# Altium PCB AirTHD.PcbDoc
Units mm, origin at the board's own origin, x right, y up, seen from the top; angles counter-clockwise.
Board outline 25.5 x 27.05 mm, 2 copper layers (Top Layer, Bottom Layer); 29 components, 49 nets, 170 pads, 71 vias.
Unrouted connection lines stored in the file: 1.
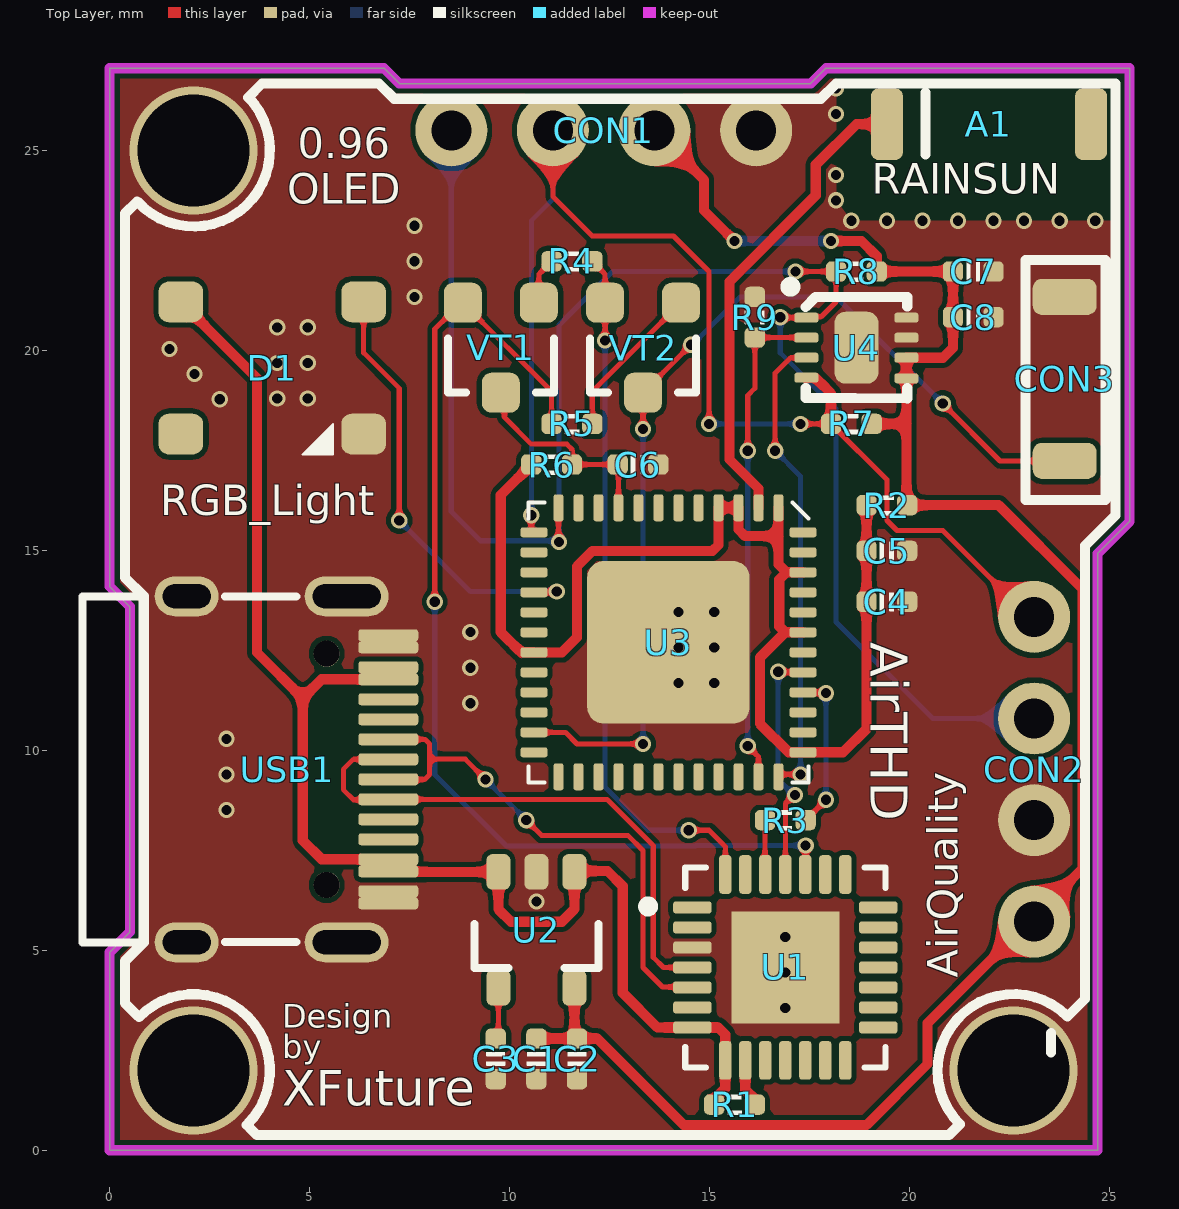
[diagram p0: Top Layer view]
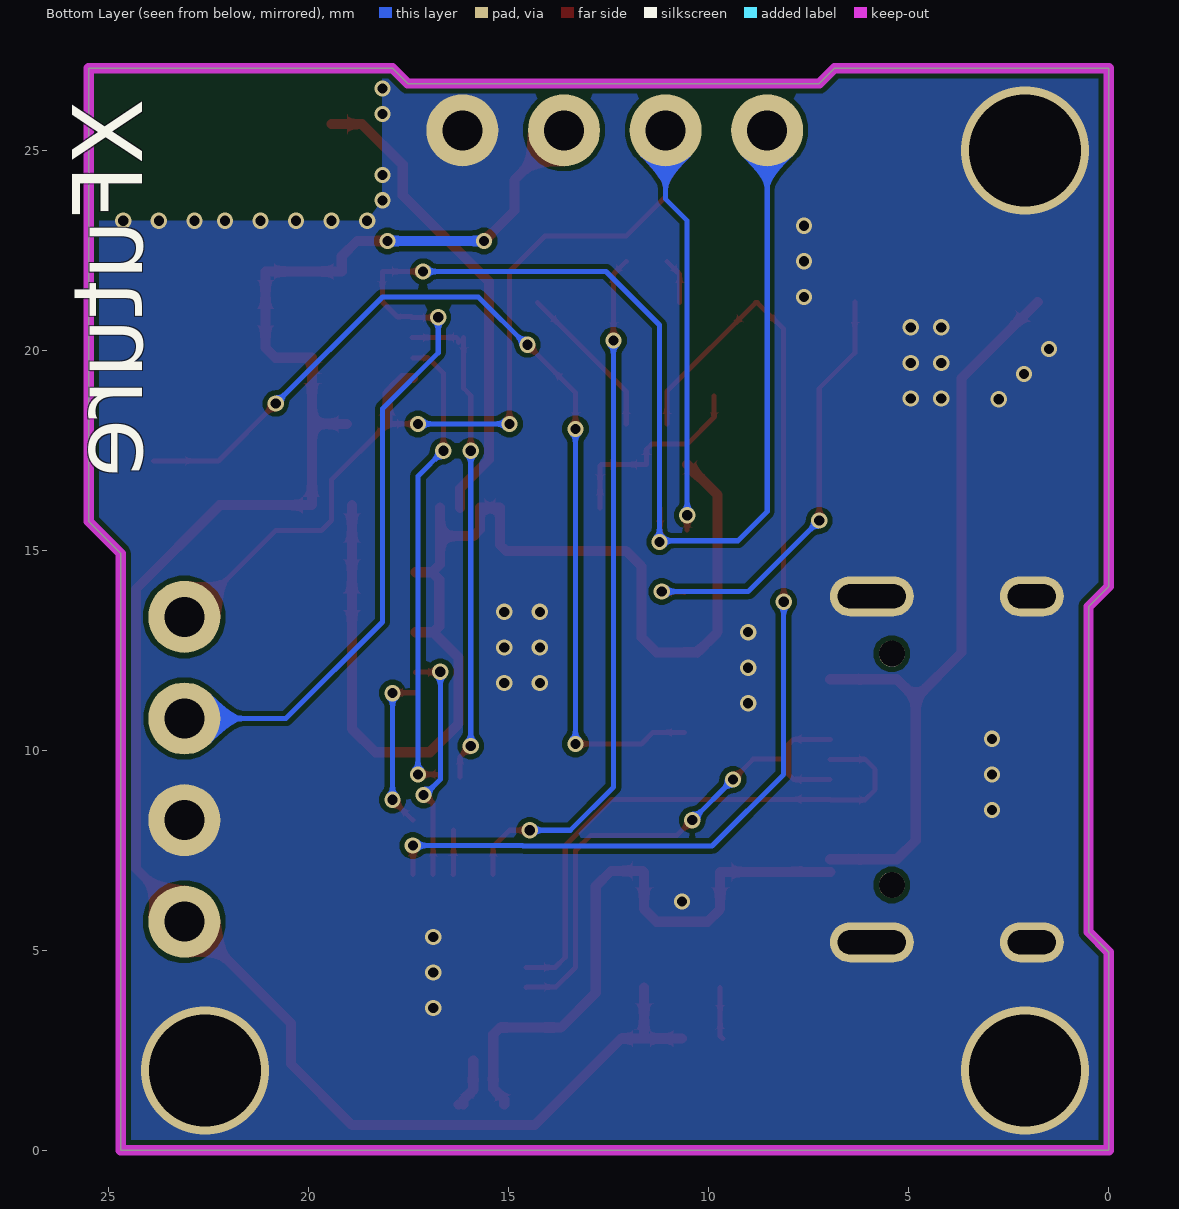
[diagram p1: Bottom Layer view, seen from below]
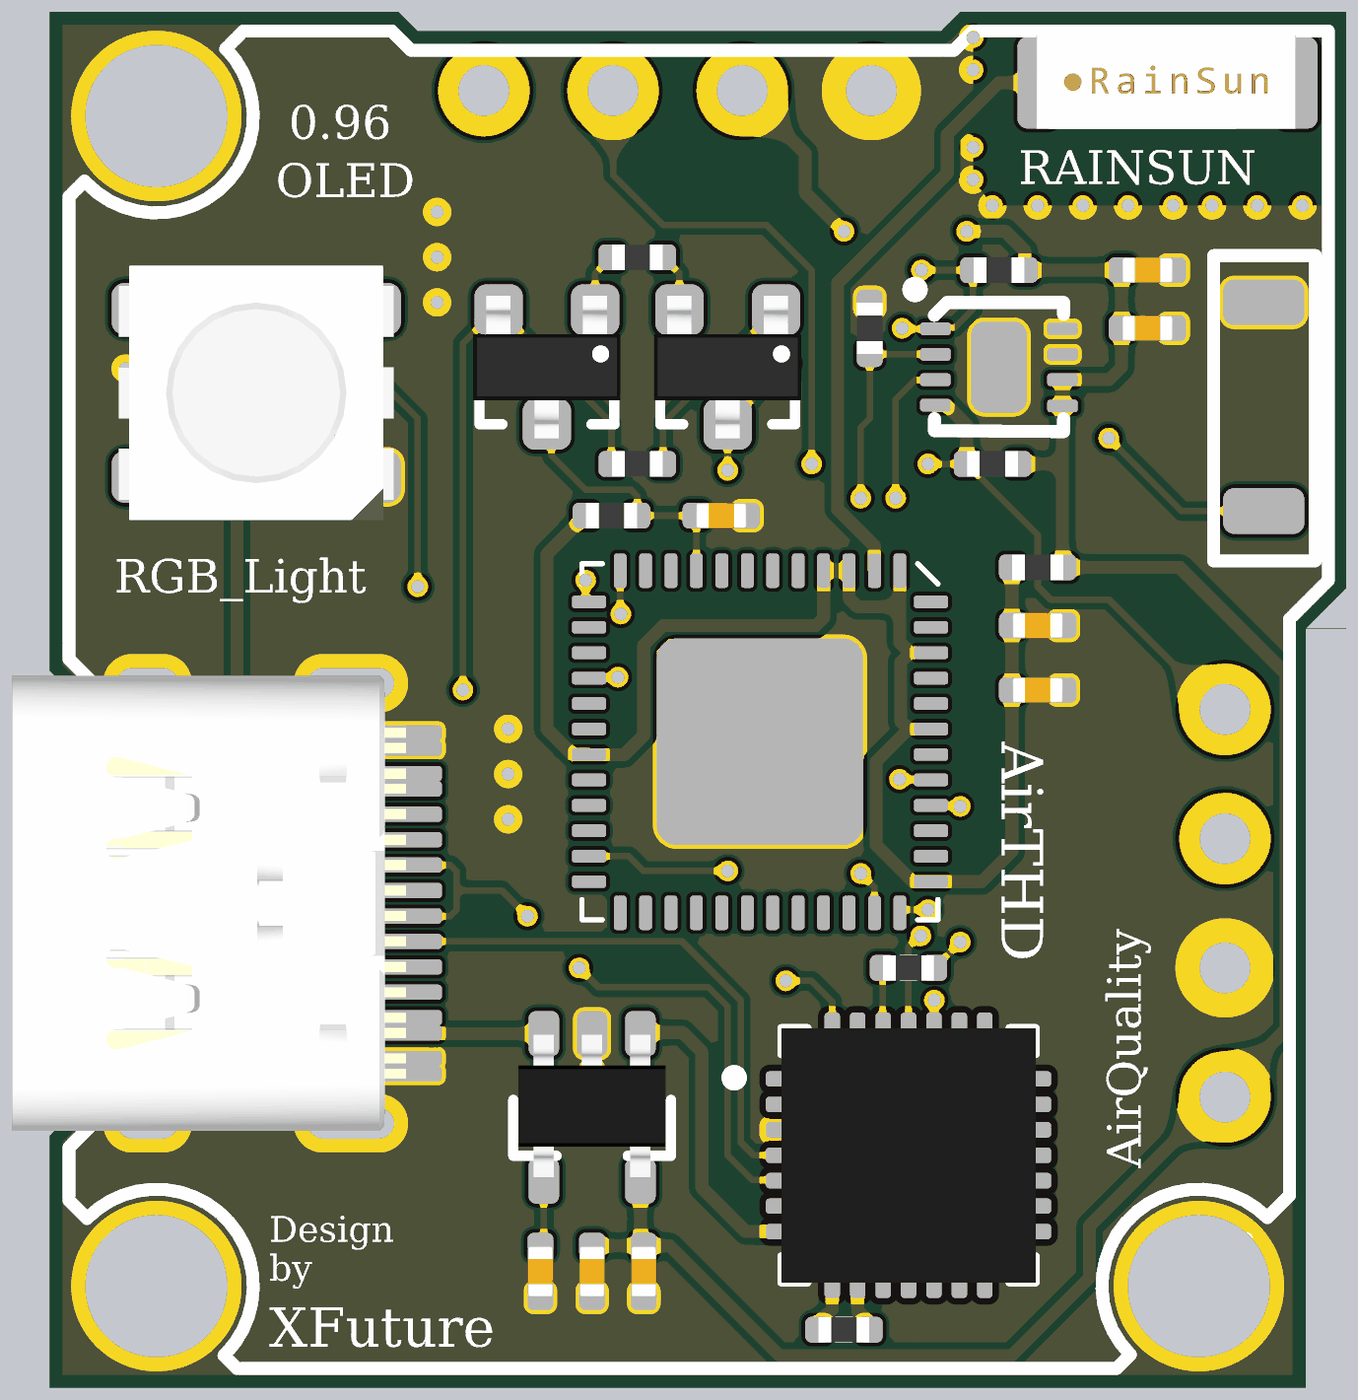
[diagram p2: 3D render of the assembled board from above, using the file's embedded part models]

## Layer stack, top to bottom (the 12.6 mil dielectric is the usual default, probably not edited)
Top Solder: solder mask 0.0102, Solder Resist, Dk 3.5
Top Layer: signal copper 0.0356
Dielectric 1: dielectric 0.32, FR-4, Dk 4.8
Bottom Layer: signal copper 0.0356
Bottom Solder: solder mask 0.0102, Solder Resist, Dk 3.5

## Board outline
0,0 0,4.953 0.508,5.461 0.508,13.589 0,14.097 0,27.051 6.858,27.051 7.239,26.67 17.526,26.67 17.907,27.051 25.5,27.051 25.5,15.721 24.7,14.921 24.7,0

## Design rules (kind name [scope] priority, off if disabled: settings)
Clearance [All] p1: gap=0.127 ignorepadtopadclearanceinfootprint=FALSE
ComponentClearance [All] p1: gap=0 collisioncheckmode=3 verticalgap=0 showdistances=FALSE
DiffPairsRouting [All] p1: maxlimit=0.229 minlimit=0.229 mostfreqgap=0.229 toplayer_minwidth=0.102 toplayer_maxwidth=0.102 toplayer_prefwidth=0.102 bottomlayer_minwidth=0.102 bottomlayer_maxwidth=0.102 bottomlayer_prefwidth=0.102 maxuncoupledlength=12.7
FanoutControl Fanout_BGA [All] p1: bgadir=Out bgaviamode=Centered fanoutstyle=Auto fanoutdirection=Alternating viagrid=0.025 // Fanout_BGA (Default Rule)
HoleSize [All] p1: absolutevalues=TRUE maxlimit=254 minlimit=0.203 maxpercent=80.000 minpercent=20.000
MinimumSolderMaskSliver [All] p1 off: minsoldermaskwidth=0.051
PlaneClearance [All] p1: clearance=0.203
PlaneConnect [All] p1: planeconnectstyle=Direct reliefexpansion=0.508 reliefentries=4 reliefconductorwidth=0.254 reliefairgap=0.254
PolygonConnect [All] p1: connectstyle=Direct reliefconductorwidth=0.254 reliefentries=4 polygonreliefangle="90 Angle" airgapwidth=0.254
RoutingVias [All] p1: holewidth=0.203 width=0.406 viastyle="Through Hole" minholewidth=0.152 minwidth=0.305 maxholewidth=0.711 maxwidth=1.27
SilkToSilkClearance [All] p1: silktosilkclearance=0
SilkToSolderMaskClearance [IsPad] p1: minsilkscreentomaskgap=0 clearancetoexposedcopper=TRUE
SolderMaskExpansion [All] p1: expansion=0.076 istentingtop=FALSE
Width [All] p1: maxlimit=254 minlimit=0.102 preferedwidth=0.127
21 further rules are at their usual default settings.

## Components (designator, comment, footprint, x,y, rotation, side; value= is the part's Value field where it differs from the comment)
A1 "RAINSUN" ANT-Rainsun-AN5120 21.971,25.654 r0 top
C1 "0.1uF" CAP_0402 10.668,2.286 r90 top value=0.1u
C2 "10uF" CAP_0402 11.684,2.286 r90 top value=0.1u
C3 "10nF" CAP_0402 9.652,2.286 r90 top value=0.1u
C4 "10uF" CAP_0402 19.431,13.716 r180 top value=0.1u
C5 "0.1uF" CAP_0402 19.431,14.986 r180 top value=0.1u
C6 "0.1uF" CAP_0402 13.208,17.145 r0 top value=0.1u
C7 "0.1uF" CAP_0402 21.59,21.971 r180 top value=0.1u
C8 "4.7uF" CAP_0402 21.59,20.828 r180 top value=0.1u
CON1 "0.96_OLED" 4Pin排针 12.35,25.5 r180 top
CON2 "SGP30" 4Pin排针 23.114,9.525 r90 top
CON3 "按钮" 3*4贴片按钮 23.749,19.431 r270 top
D1 "RGB" LED_5050_WS2812B 4.064,19.558 r0 top
R1 "10K" RES_0402 15.621,1.143 r0 top value=22R
R2 "0R" RES_0402 19.431,16.129 r180 top value=22R
R3 "200R" RES_0402 16.891,8.255 r180 top value=22R
R4 "12K" RES_0402 11.557,22.225 r180 top value=22R
R5 "12K" RES_0402 11.557,18.161 r0 top value=22R
R6 "10K" RES_0402 11.049,17.145 r0 top value=22R
R7 "10K" RES_0402 18.542,18.161 r0 top value=22R
R8 "10K" RES_0402 18.669,21.971 r0 top value=22R
R9 "10K" RES_0402 16.129,20.828 r270 top value=22R
U1 "CP2102" QFN-28 16.891,4.572 r0 top value=Value
U2 "LP2992 3V3" SOT23-5 10.668,5.461 r270 top
U3 "ESP32_SIP" QFN-48_7X7 13.97,12.7 r270 top
U4 "SHT30" SHT30 18.669,20.066 r0 top
USB1 "Type-C" Type-C-TOP 4.445,9.525 r180 top
VT1 "S8050" SMT_TRIODE_NPN 9.779,20.066 r180 top
VT2 "S8050" SMT_TRIODE_NPN 13.335,20.066 r180 top

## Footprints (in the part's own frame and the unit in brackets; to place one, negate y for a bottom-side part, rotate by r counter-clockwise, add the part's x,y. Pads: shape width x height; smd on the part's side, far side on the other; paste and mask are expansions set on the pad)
3*4贴片按钮 [mm]
  rrect50% 0.9x1.6 smd: 1(-1.905,0.127) 2(2.195,0.127)
  silkscreen extent -2.83,-0.86 3.17,1.14, body extent -2.79,-0.89 3.17,1.14, height 0.25
4Pin排针 [mm]
  round 1.8 hole 1: 1(-3.81,0) 2(-1.27,0) 3(1.27,0) 4(3.81,0)
  body extent -5.21,-1.27 5.21,1.27, height 0.25
ANT-Rainsun-AN5120 [mm]
  rrect50% 0.8x1.8 smd: 1(-2.54,0) ""(2.563,0)
  silkscreen extent -1.57,-0.76 -1.57,0.79, body extent -2.57,-0.91 2.54,0.94, height 1.32
CAP_0402 [mil]
  rrect50% 20x20 smd: 1(-20,0) 2(20,0)
  silkscreen extent -7,-9 7,9, body extent -20,-10 20,10, height 20
LED_5050_WS2812B [mil]
  rrect50% 44x40 smd: 1(-90,65) 2(-90,-65) 3(90,-65) 4(90,65)
  silkscreen extent 30,-85 60,-55, body extent -106,-98 106,98, height 69
QFN-28 [mil]
  rrect50% 38x12 smd mask+5: 1(-91.5,59.06) 2(-91.5,39.37) 3(-91.5,19.68) 4(-91.5,0) 5(-91.5,-19.68) 6(-91.5,-39.37) 7(-91.5,-59.06) 15(91.5,-59.06) 16(91.5,-39.37) 17(91.5,-19.68) 18(91.5,0) 19(91.5,19.68) 20(91.5,39.37) 21(91.5,59.06)
  rrect50% 12x38 smd mask+5: 8(-59.06,-91.5) 9(-39.37,-91.5) 10(-19.69,-91.5) 11(0,-91.5) 12(19.69,-91.5) 13(39.37,-91.5) 14(59.06,-91.5) 22(59.06,91.5) 23(39.37,91.5) 24(19.69,91.5) 25(0,91.5) 26(-19.69,91.5) 27(-39.37,91.5) 28(-59.06,91.5)
  rect 106.3x110.24 smd: 29(0,0)
  silkscreen extent -140,-98 98,98, body extent -98,-98 98,98, height 35
QFN-48_7X7 [mm]
  rrect20% 4.064x4.064 smd: 0(0,0)
  rrect50% 0.675x0.25 smd: 1(-3.362,2.75) 2(-3.362,2.25) 3(-3.363,1.75) 4(-3.363,1.25) 5(-3.363,0.75) 6(-3.362,0.25) 7(-3.362,-0.25) 8(-3.362,-0.75) 9(-3.362,-1.25) 10(-3.362,-1.75) 11(-3.363,-2.25) 12(-3.363,-2.75) 25(3.363,-2.75) 26(3.363,-2.25) 27(3.363,-1.75) 28(3.363,-1.25) 29(3.363,-0.75) 30(3.362,-0.25) 31(3.362,0.25) 32(3.363,0.75) 33(3.363,1.25) 34(3.363,1.75) 35(3.363,2.25) 36(3.363,2.75)
  rrect50% 0.25x0.675 smd: 13(-2.75,-3.363) 14(-2.25,-3.363) 15(-1.75,-3.363) 16(-1.25,-3.363) 17(-0.75,-3.363) 18(-0.25,-3.362) 19(0.25,-3.362) 20(0.75,-3.363) 21(1.25,-3.363) 22(1.75,-3.363) 23(2.25,-3.363) 24(2.75,-3.363) 37(2.75,3.363) 38(2.25,3.363) 39(1.75,3.362) 40(1.25,3.362) 41(0.75,3.362) 42(0.25,3.362) 43(-0.25,3.362) 44(-0.75,3.363) 45(-1.25,3.363) 46(-1.75,3.363) 47(-2.25,3.362) 48(-2.75,3.362)
  silkscreen extent -3.5,-3.5 3.5,3.5, body extent -3.5,-3.5 3.5,3.5, height 1
RES_0402 [mil]
  rrect50% 20x20 smd: 1(-20,0) 2(20,0)
  silkscreen extent -6,-10 6,10, body extent -20,-10 20,10, height 14
SHT30 [mm]
  rrect50% 0.6x0.25 smd: 1(-1.25,0.75) 2(-1.25,0.25) 3(-1.25,-0.25) 4(-1.25,-0.75) 5(1.25,-0.766) 6(1.25,-0.25) 7(1.25,0.25) 8(1.25,0.75)
  rrect50% 1.1x1.8 smd: 9(0,0)
  silkscreen extent -1.78,-1.27 1.27,1.65, body extent -1.27,-1.27 1.27,1.27, height 0.25
SMT_TRIODE_NPN [mm]
  rrect50% 0.95x1 smd: 1(-0.95,-1.125) 2(0.95,-1.125) 3(0,1.125)
  silkscreen extent -1.33,-0.22 1.32,1.13, body extent -1.45,-1.4 1.45,1.4, height 1.3
SOT23-5 [mm]
  rrect50% 0.889x0.6 smd: 1(-1.5,0.95) 2(-1.5,0) 3(-1.5,-0.95) 4(1.396,-0.95) 5(1.396,0.95)
  silkscreen extent -0.2,-1.55 0.9,1.55, body extent -1.48,-1.45 1.32,1.45, height 1.2
Type-C-TOP [mm]
  round 0.65 hole 0.65: 0(-0.98,2.89) 0(-0.98,-2.89)
  oval 1.6x1 hole 0.6 slot 1.2 at 0 deg: 1(2.52,4.325) 2(2.52,-4.325)
  oval 2.1x1 hole 0.6 slot 1.7 at 0 deg: 3(-1.48,-4.325) 4(-1.48,4.325)
  rrect50% 1.5x0.3 smd: A1(-2.52,-3.35) A4(-2.52,-2.55) A5(-2.52,-1.25) A6(-2.52,-0.25) A7(-2.52,0.25) A8(-2.52,1.25) A9(-2.52,2.55) A12(-2.52,3.35) B1(-2.52,3.05) B4(-2.52,2.25) B5(-2.52,1.75) B6(-2.52,0.75) B7(-2.52,-0.75) B8(-2.52,-1.75) B9(-2.52,-2.25) B12(-2.52,-3.05)
  silkscreen extent -0.22,-4.33 5.12,4.33, body extent -2.57,-4.48 5.18,4.48, height 3.26

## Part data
A1: library part ANT-Rainsun-AP5120
C1 C2 C3 C4 C5 C6 C7 C8: library part 电容-0402, "Capacitor"
D1: library part LED_5050_WS2812B, "LED"
R1 R2 R3 R4 R5 R6 R7 R8 R9: library part 电阻-0402, "Resistor"
U1: "USB转TTL"
U2: library part LP2992, "LDO"
U3: library part ESP32-PICO
USB1: library part USB-Type-C-TOP
VT1 VT2: library part SMT_TRIODE_NPN, "Surface mount NPN transistor, package SOT-23"

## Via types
v1: diameter 0.406, hole 0.254, Top Layer to Bottom Layer, 68 vias
v2: diameter 3.2, hole 2.8, Top Layer to Bottom Layer, 3 vias

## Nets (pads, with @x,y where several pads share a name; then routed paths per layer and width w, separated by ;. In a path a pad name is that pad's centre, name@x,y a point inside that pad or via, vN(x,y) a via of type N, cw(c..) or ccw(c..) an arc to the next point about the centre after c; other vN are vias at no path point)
3V3: C1.2 C2.2 C7.2 C8.2 CON1.2 CON2.1 R2.1 R7.2 R8.2 U2.5 U4.5 U4.6 | length 48.7
  Top Layer w0.254: C1.2 C2.2 ; U2.5 11.618,2.86 C2.2 ; CON1.2 14.859,24.261 14.859,23.495 v1(15.621,22.733) ; v1(18.034,22.733) 18.796,22.733 19.177,22.352 R8.2 C7.2 C8.2 21.082,20.066 20.832,19.816 U4.6 U4.5 19.919,18.161 ; R7.2 19.919,18.161 ; R2.1@19.919,16.129 19.919,18.161 ; R2.1 22.225,16.129 24.319,14.035 24.319,7.047 20.447,3.175 20.447,2.159 18.923,0.635 14.351,0.635 12.192,2.794 C2.2
  Bottom Layer w0.254: v1(15.621,22.733) v1(18.034,22.733)
3V3A: C4.2 C5.2 R2.2 R6.1 U3.1 U3.3 U3.4 U3.19 U3.37 U3.43 U3.46 | length 30.9
  Top Layer w0.254: R6.1 9.779,16.383 9.779,12.954 10.283,12.45 U3.19 10.61,12.448 10.859,12.448 10.861,12.446 11.303,12.446 11.684,12.827 11.684,14.599 12.071,14.986 15.071,14.986 15.22,15.135 U3.4 U3.3 15.72,15.522 15.886,15.356 16.72,15.356 ; U3.1 16.72,15.356 ; U3.43 16.89,12.95 ; U3.46 16.919,14.45 ; R2.2 C5.2 C4.2 18.923,10.541 18.332,9.95 16.974,9.95 16.256,10.668 16.256,12.316 16.89,12.95 ; 16.72,15.356 16.72,14.649 16.919,14.45 ; 16.89,12.95 16.741,13.099 16.741,14.272 16.919,14.45
ADDR: R9.2 U3.35 U4.2 | length 12.4
  Top Layer w0.127: v1(15.951,10.109) 16.22,9.84 U3.35 ; v1(15.951,17.488) 15.951,18.872 16.129,19.05 R9.2 ; R9.2@16.256,20.193 16.256,20.261 16.315,20.32 17.415,20.32 U4.2
  Bottom Layer w0.127: v1(15.951,10.109) v1(15.951,17.488)
Air_SCL: CON1.3 CON2.4 R7.1 U3.13 U4.4 | length 32.5
  Top Layer w0.127: U3.13@10.541,15.512 v1(10.541,15.875) ; CON1.3 11.08,23.845 12.065,22.86 14.097,22.86 14.986,21.971 v1(14.986,18.161) ; v1(17.272,18.161) R7.1 19.431,16.764 19.431,15.748 19.685,15.494 20.828,15.494 CON2.4@22.987,13.335
  Top Layer w0.254: U4.4@17.399,19.304 17.653,19.304 18.034,18.923 R7.1
  Bottom Layer w0.127: v1(10.541,15.875) 10.541,23.241 11.08,23.78 CON1.3 ; v1(14.986,18.161) v1(17.272,18.161)
Air_SDA: CON1.4 CON2.3 R8.1 U3.12 U4.1 | length 42.6
  Top Layer w0.127: v1@11.22,15.225 U3.12 ; v1@16.776,20.816 U4.1 17.446,20.843 17.795,20.843 18.161,21.209 R8.1 v1(17.145,21.971)
  Bottom Layer w0.127: CON1.4 8.54,15.971 9.271,15.24 11.205,15.24 v1(11.233,15.211) 11.233,20.631 12.573,21.971 v1(17.145,21.971) ; v1(16.764,20.828) 16.764,19.939 18.161,18.542 18.161,13.208 20.574,10.795 CON2.3@22.987,10.795
ALERT: U3.36 U4.3 | length 11.8
  Top Layer w0.127: v1(16.637,17.488) 16.637,19.431 17.018,19.812 U4.3@17.399,19.812 ; U3.36 16.781,9.398 v1(17.272,9.398)
  Bottom Layer w0.127: v1(16.637,17.488) 17.272,16.853 v1(17.272,9.398)
CP_Rx: U1.25 U3.41 | length 5.9
  Top Layer w0.127: v1(16.713,11.963) 16.72,11.957 17.326,11.957 U3.41 ; U1.25 16.891,8.673 v1@17.102,8.883
  Bottom Layer w0.127: v1(16.713,11.963) 16.713,9.272 v1@17.102,8.883
  other v1: 17.132,8.883
CP_Tx: R3.1 U3.40 | length 4
  Top Layer w0.127: U3.40 17.342,11.44 17.897,11.44 v1(17.907,11.43) ; R3.1 v1(17.907,8.763)
  Bottom Layer w0.127: v1(17.907,8.763) v1(17.907,11.43)
DTR: R4.1 U1.28 VT2.2 | length 17.6
  Top Layer w0.127: R4.1 12.385,21.905 VT2.2 v1(12.385,20.245) ; v1(14.478,8.001) 14.986,8.001 15.391,7.596 U1.28
  Bottom Layer w0.127: v1(12.385,20.245) 12.385,9.078 13.462,8.001 v1(14.478,8.001)
EN: C6.1 R6.2 U3.9 VT1.3 | length 5.1
  Top Layer w0.127: VT1.3@9.869,18.851 9.869,18.325 10.541,17.653 11.43,17.653 11.557,17.526 R6.2 C6.1 ; U3.9 C6.1@12.72,17.125
FLASH_CLK: U3.31
FLASH_CS: U3.25
FLASH_SD0: U3.27
FLASH_SD1: U3.33
FLASH_SD2: U3.30
FLASH_SD3: U3.32
GND: C1.1 C2.1 C3.1 C4.1 C5.1 C6.2 C7.1 C8.1 CON1.1 CON2.2 CON3.1 D1.3 R9.1 U1.3 U1.29 U2.2 U3.0 U4.7 U4.8 U4.9 USB1.1 USB1.2 USB1.3 USB1.4 USB1.A1 USB1.A12 USB1.B1 USB1.B12
  other v1: 16.891,3.556 16.891,4.445 16.891,5.334 10.668,6.223 2.921,8.509 2.921,9.398 2.921,10.287 9.017,11.176 14.224,11.684 15.113,11.684 9.017,12.065 14.224,12.573 15.113,12.573 9.017,12.954 14.224,13.462 15.113,13.462 2.75,18.778 4.191,18.796 4.953,18.796 2.122,19.407 4.191,19.685 4.953,19.685 1.493,20.035 4.191,20.574 4.953,20.574 7.62,21.336 7.62,22.225 7.62,23.114 18.542,23.241 19.431,23.241 20.32,23.241 21.209,23.241 22.098,23.241 22.86,23.241 23.749,23.241 24.638,23.241 18.161,23.749 18.161,24.384 18.161,25.908 18.161,26.543
  other v2: 2.1,2 22.6,2 2.1,25
GPIO0: CON3.2 U3.23 VT2.3 | length 24.9
  Top Layer w0.127: U3.23 11.394,10.45 11.684,10.16 v1(13.335,10.16) ; v1(13.335,18.034) VT2.3 v1(14.534,20.14) ; v1(20.828,18.669) 22.261,17.236 CON3.2
  Bottom Layer w0.127: v1(13.335,10.16) v1(13.335,18.034) ; v1(14.534,20.14) 14.567,20.14 15.764,21.336 18.161,21.336 v1(20.828,18.669)
GPIO2: U3.22
GPIO4: U3.24
GPIO5: U3.34
GPIO9: U3.28
GPIO10: U3.29
GPIO12: U3.18
GPIO13: U3.20
GPIO14: U3.17
GPIO15: U3.21
GPIO19: U3.38
GPIO21: U3.42
GPIO22: U3.39
GPIO25: U3.14
GPIO26: U3.15
GPIO27: D1.4 U3.16 | length 11.1
  Top Layer w0.127: D1.4 6.35,19.939 7.239,19.05 v1(7.239,15.748) ; U3.16 10.617,13.96 11.166,13.96 v1(11.176,13.97)
  Bottom Layer w0.127: v1(7.239,15.748) 9.017,13.97 v1(11.176,13.97)
GPIO34: U3.10
GPIO35: U3.11
GPIO37: U3.6
GPIO38: U3.7
NetA1_1: A1.1 U3.2 | length 12
  Top Layer w0.254: U3.2 16.22,16.546 15.494,17.272 15.494,21.717 17.653,23.876 17.653,24.638 18.669,25.654 A1.1
NetC3_2: C3.2 U2.4 | length 1.3
  Top Layer w0.127: C3.2 9.718,2.86 U2.4
NetR1_2: R1.2 U1.9 | length 1.2
  Top Layer w0.254: U1.9@15.895,2.244 U1.9 15.891,1.508 16.129,1.27 R1.2
NetR3_2: R3.2 U1.26 | length 1.1
  Top Layer w0.127: R3.2@16.383,8.001 16.383,6.904 U1.26
NetR4_2: R4.2 VT1.1 | length 1.2
  Top Layer w0.127: VT1.1 10.729,21.905 R4.2
NetR5_2: R5.2 VT2.1 | length 3.9
  Top Layer w0.127: R5.2 12.065,18.971 VT2.1
RTS: R5.1 U1.24 VT1.2 | length 26.8
  Top Layer w0.127: v1(8.128,13.716) 8.128,20.532 VT1.2@8.787,21.191 ; VT1.2 11.049,18.971 R5.1 ; U1.24 17.395,6.9 17.395,7.616 v1(17.399,7.62)
  Bottom Layer w0.127: v1(8.128,13.716) 8.128,9.398 9.919,7.607 14.641,7.607 14.654,7.62 v1(17.399,7.62)
SENSOR_VN: U3.8
SENSOR_VP: U3.5
USB-PWR-DM: U1.5 USB1.A7 USB1.B7 | length 13.6
  Top Layer w0.127: USB1.B7 7.886,10.275 8.001,10.16 8.001,9.779 ; USB1.A7@6.969,9.271 7.874,9.271 8.001,9.398 8.001,9.779 ; v1(9.398,9.271) 8.89,9.779 8.001,9.779 ; v1(10.414,8.255) 10.795,7.874 12.954,7.874 13.335,7.493 13.335,4.572 13.824,4.083 14.556,4.083 U1.5
  Bottom Layer w0.127: v1(9.398,9.271) v1(10.414,8.255)
USB-PWR-DP: U1.4 USB1.A6 USB1.B6 | length 13.9
  Top Layer w0.127: USB1.B6@6.953,8.763 6.096,8.763 5.842,9.017 5.842,9.525 6.092,9.775 USB1.A6 ; USB1.B6 12.434,8.775 13.589,7.62 13.589,4.826 13.843,4.572 U1.4
VDD_5V: D1.1 R1.1 U1.7 U1.8 U2.1 U2.3 USB1.A4 USB1.A9 USB1.B4 USB1.B9 | length 35
  Top Layer w0.254: D1.1 3.683,19.304 3.683,12.446 4.826,11.303 ; USB1.A9@6.965,6.961 U2.3 9.718,6.03 10.033,5.715 11.303,5.715 11.618,6.03 U2.1 ; USB1.B4 5.298,7.275 4.826,7.747 4.826,11.303 ; USB1.B9 5.298,11.775 4.826,11.303 ; U2.1@11.642,6.985 12.446,6.985 12.827,6.604 12.827,3.937 13.692,3.072 U1.7 15.216,3.072 15.391,2.897 U1.8 15.391,1.548 15.113,1.27 R1.1
pads on no net: A1. D1.2 U1.1 U1.2 U1.6 U1.10 U1.11 U1.12 U1.13 U1.14 U1.15 U1.16 U1.17 U1.18 U1.19 U1.20 U1.21 U1.22 U1.23 U1.27 U3.26 U3.44 U3.45 U3.47 U3.48 USB1.0 USB1.A5 USB1.A8 USB1.B5 USB1.B8

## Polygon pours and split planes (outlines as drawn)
GND on Bottom Layer "GND_L02_P000" (solid, remove dead copper, pour order 0): 0,27.051 25.527,27.051 25.527,0 0,0
GND on Top Layer "GND_L01_P002" (solid, remove dead copper, pour order 2): 0,27.051 25.527,27.051 25.527,0 0,0

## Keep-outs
Keep-Out Layer:
  the board outline again, w0.254

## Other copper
Top Layer:
  pour cut-out: 25.654,23.241 18.542,23.241 18.161,23.749 18.161,27.242 25.654,27.242
Bottom Layer:
  pour cut-out: 25.654,23.241 18.542,23.241 18.161,23.749 18.161,27.242 25.654,27.242

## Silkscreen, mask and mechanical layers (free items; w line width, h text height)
Top Overlay:
  lines w0.254: 0.735,3.329 cw(c2.1,2) 3.429,0.635 ; 0.753,3.347 0.717,3.347 0.381,3.683 0.381,4.728 0.853,5.2 0.853,13.85 0.381,14.322 0.381,14.605 0.381,23.368 0.381,23.416 0.687,23.722 ccw(c2.1,25) 3.467,26.327 ; 3.461,26.321 3.81,26.67 6.731,26.67 7.112,26.289 17.399,26.289 17.526,26.289 17.78,26.289 18.161,26.67 25.146,26.67 25.146,22.352 25.146,15.875 24.384,15.113 24.384,3.784 23.947,3.347 ccw(c22.6,2) 21.24,0.666 ; 3.483,0.617 3.483,0.581 3.683,0.381 20.981,0.381 21.253,0.653 ; 23.533,2.451 23.533,2.933
  text "0.96" at 4.699,24.552 h1.3
  text "RAINSUN" at 19.05,23.663 h1.3
  text "OLED" at 4.445,23.409 h1.3
  text "RGB_Light" at 1.27,15.629 h1.3
  text "AirTHD" at 18.719,12.7 h1.6 r270
  text "AirQuality" at 21.455,4.318 h1.3 r90
  text "Design" at 4.318,2.869 h1
  text "by" at 4.318,2.107 h1
  text "XFuture" at 4.318,0.81 h1.52
Bottom Overlay:
  text "XFuture" at 23.587,26.289 h3 r270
